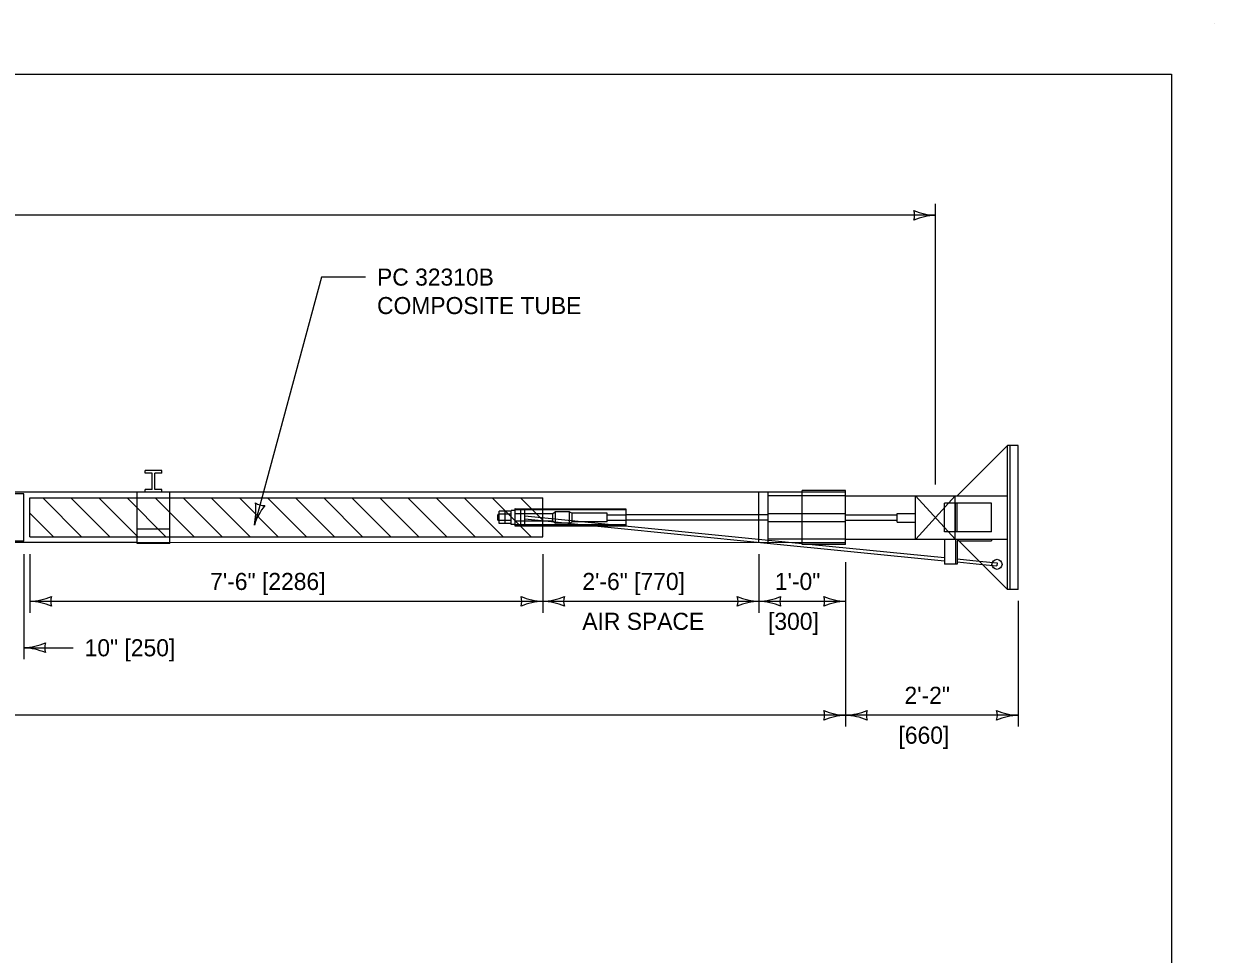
# Model space of a CAD drawing. Extents: x 49991.4 to 50021, y 49987.6 to 50011.4.
# Drawn here: x 50012.718 to 50016.9, y 49995.907 to 49999.176 of the extents above; entities that cross this region are included whole.
import ezdxf

# ---------------------------------------------------------------- set-up
doc = ezdxf.new("R2010")
doc.units = 0
for name, color, linetype in [('Level 1', 7, 'Continuous'), ('Level 2', 7, 'Continuous'), ('Level 3', 7, 'Continuous'), ('Level 4', 7, 'Continuous'), ('Level 5', 7, 'Continuous')]:
    doc.layers.add(name, color=color, linetype=linetype)

msp = doc.modelspace()

# ---------------------------------------------------------------- linework, layer by layer
at = {"layer": 'Level 1'}
for p, q in [((50016.9001, 49999.1756), (50016.9001, 49999.1756)), ((50016.1742, 49997.6945), (50015.9971, 49997.5172)), ((50016.1742, 49997.1881), (50016.1742, 49997.6945)), ((50016.2117, 49997.6945), (50016.1742, 49997.6945)), ((50016.1838, 49997.1881), (50016.1838, 49997.6945)), ((50016.2117, 49997.1881), (50016.2117, 49997.6945)), ((50013.1443, 49997.5969), (50013.1443, 49997.606)), ((50013.2033, 49997.606), (50013.1443, 49997.606)), ((50013.1693, 49997.5969), (50013.1443, 49997.5969)), ((50013.1693, 49997.5393), (50013.1693, 49997.5969)), ((50013.1784, 49997.5393), (50013.1784, 49997.5969)), ((50013.2033, 49997.5969), (50013.1784, 49997.5969)), ((50013.2033, 49997.5969), (50013.2033, 49997.606)), ((50015.4527, 49997.53), (50008.363, 49997.5304)), ((50013.1693, 49997.5393), (50013.1443, 49997.5393)), ((50013.1443, 49997.5301), (50013.1443, 49997.5393)), ((50013.2033, 49997.5393), (50013.1784, 49997.5393)), ((50013.2033, 49997.5301), (50013.2033, 49997.5393)), ((50015.4527, 49997.3467), (50015.4527, 49997.5361)), ((50015.6047, 49997.536), (50015.4527, 49997.5361)), ((50015.6047, 49997.3467), (50015.6047, 49997.536)), ((50015.6047, 49997.5173), (50016.1742, 49997.5171)), ((50015.8513, 49997.3655), (50015.8513, 49997.5172)), ((50015.8513, 49997.5172), (50015.9907, 49997.3655)), ((50015.9907, 49997.5172), (50015.8514, 49997.3655)), ((50016.1174, 49997.4921), (50015.9528, 49997.4921)), ((50015.9528, 49997.3905), (50015.9528, 49997.4921)), ((50015.9528, 49997.3932), (50015.9528, 49997.4908)), ((50015.9907, 49997.3655), (50015.9907, 49997.5172)), ((50015.9908, 49997.3905), (50015.9908, 49997.4921)), ((50015.9972, 49997.3905), (50015.9972, 49997.4921)), ((50016.1174, 49997.3905), (50016.1174, 49997.4921)), ((50015.7618, 49997.4494), (50015.6047, 49997.4494)), ((50015.7868, 49997.4494), (50015.7618, 49997.4494)), ((50015.7868, 49997.4249), (50015.7868, 49997.4557)), ((50015.7868, 49997.4557), (50015.8513, 49997.4557)), ((50015.7618, 49997.4311), (50015.6047, 49997.4311)), ((50015.7868, 49997.4311), (50015.7618, 49997.4311)), ((50015.7868, 49997.4249), (50015.8513, 49997.4249)), ((50013.2308, 49997.4004), (50013.1168, 49997.4004)), ((50013.1168, 49997.3497), (50013.1168, 49997.4003)), ((50013.2308, 49997.3498), (50013.2308, 49997.4004)), ((50015.6047, 49997.3655), (50016.1742, 49997.3653)), ((50016.1174, 49997.3905), (50015.9528, 49997.3905)), ((50015.9528, 49997.3654), (50015.9528, 49997.2768)), ((50015.9908, 49997.3654), (50015.9908, 49997.2768)), ((50016.1742, 49997.1881), (50015.9972, 49997.3654)), ((50013.1168, 49997.3529), (50011.4076, 49997.3531)), ((50013.2308, 49997.3498), (50013.1168, 49997.3498)), ((50015.4527, 49997.3527), (50013.2308, 49997.353)), ((50015.3177, 49997.3527), (50015.9528, 49997.2895)), ((50015.4275, 49997.3527), (50015.4527, 49997.3502)), ((50015.6047, 49997.3467), (50015.4527, 49997.3467)), ((50015.4878, 49997.3467), (50015.9528, 49997.3004)), ((50015.9972, 49997.359), (50015.9972, 49997.2768)), ((50016.0036, 49997.359), (50015.9972, 49997.359)), ((50015.9972, 49997.296), (50016.0741, 49997.2884)), ((50015.9972, 49997.2851), (50016.0862, 49997.2763)), ((50015.9972, 49997.2768), (50015.9528, 49997.2768)), ((50016.2117, 49997.1881), (50016.1742, 49997.1881))]:
    msp.add_line(p, q, dxfattribs=at)
msp.add_lwpolyline([(49999.3835, 49998.9992), (50016.7501, 49998.9992), (50016.7501, 49987.7988), (49999.3835, 49987.7988)], close=True, dxfattribs=at)
at = {"layer": 'Level 3'}
for p, q in [((50015.9211, 49997.5572), (50015.9211, 49998.5428)), ((50015.9211, 49998.5028), (50001.3238, 49998.5028)), ((50013.764, 49998.2858), (50013.5284, 49997.4145)), ((50013.9192, 49998.2858), (50013.764, 49998.2858)), ((50012.7185, 49997.313), (50012.7185, 49996.9436)), ((50012.7397, 49997.313), (50012.7397, 49997.1066)), ((50014.5412, 49997.3128), (50014.5412, 49997.1066)), ((50015.3009, 49997.3127), (50015.3009, 49997.1066)), ((50015.6047, 49997.2841), (50015.6047, 49996.7066)), ((50014.5412, 49997.1466), (50012.7397, 49997.1466)), ((50015.3009, 49997.1466), (50014.5412, 49997.1466)), ((50015.6047, 49997.1466), (50015.3009, 49997.1466)), ((50016.2117, 49997.1481), (50016.2117, 49996.7066)), ((50012.7185, 49996.9836), (50012.8919, 49996.9836)), ((50015.6047, 49996.7466), (50008.3123, 49996.7466)), ((50016.2117, 49996.7466), (50015.6047, 49996.7466))]:
    msp.add_line(p, q, dxfattribs=at)
for centre, radius, start, end in [((50015.9303, 49998.7249), 0.2223, 247.456, 267.6395), ((50015.7929, 49998.5028), 0.0548, 342.1388, 17.8612), ((50015.9326, 49998.2701), 0.233, 92.8273, 112.0772), ((50013.3007, 49997.4653), 0.233, 347.4771, 6.7269), ((50013.5621, 49997.5384), 0.0548, 236.7886, 272.511), ((50013.74, 49997.3471), 0.2223, 142.1058, 162.2893), ((50012.7282, 49997.3793), 0.233, 272.8273, 292.0772), ((50012.8679, 49997.1466), 0.0548, 162.1388, 197.8612), ((50014.5504, 49997.3687), 0.2223, 247.456, 267.6395), ((50014.413, 49997.1466), 0.0548, 342.1388, 17.8612), ((50014.5297, 49997.3793), 0.233, 272.8273, 292.0772), ((50014.6694, 49997.1466), 0.0548, 162.1388, 197.8612), ((50015.3101, 49997.3687), 0.2223, 247.456, 267.6395), ((50015.1727, 49997.1466), 0.0548, 342.1388, 17.8612), ((50015.2894, 49997.3793), 0.233, 272.8273, 292.0772), ((50015.4291, 49997.1466), 0.0548, 162.1388, 197.8612), ((50015.6139, 49997.3687), 0.2223, 247.456, 267.6395), ((50015.4765, 49997.1466), 0.0548, 342.1388, 17.8612), ((50012.7305, 49996.9245), 0.2223, 67.456, 87.6395), ((50014.5527, 49996.9139), 0.233, 92.8273, 112.0772), ((50014.532, 49996.9245), 0.2223, 67.456, 87.6395), ((50015.3124, 49996.9139), 0.233, 92.8273, 112.0772), ((50015.2917, 49996.9245), 0.2223, 67.456, 87.6395), ((50015.6162, 49996.9139), 0.233, 92.8273, 112.0772), ((50012.707, 49997.2163), 0.233, 272.8273, 292.0772), ((50012.8467, 49996.9836), 0.0548, 162.1388, 197.8612), ((50012.7093, 49996.7614), 0.2223, 67.456, 87.6395), ((50015.6139, 49996.9687), 0.2223, 247.456, 267.6395), ((50015.4765, 49996.7466), 0.0548, 342.1388, 17.8612), ((50015.6162, 49996.5139), 0.233, 92.8273, 112.0772), ((50015.5932, 49996.9793), 0.233, 272.8273, 292.0772), ((50015.5955, 49996.5245), 0.2223, 67.456, 87.6395), ((50015.7329, 49996.7466), 0.0548, 162.1388, 197.8612), ((50016.2209, 49996.9687), 0.2223, 247.456, 267.6395), ((50016.0835, 49996.7466), 0.0548, 342.1388, 17.8612), ((50016.2232, 49996.5139), 0.233, 92.8273, 112.0772)]:
    msp.add_arc(centre, radius, start, end, dxfattribs=at)
at = {"layer": 'Level 4'}
for p, q in [((50013.1168, 49997.4004), (50013.1168, 49997.5301)), ((50013.2308, 49997.4004), (50013.2308, 49997.5301)), ((50015.3009, 49997.3528), (50015.3009, 49997.53)), ((50015.3329, 49997.3528), (50015.333, 49997.53)), ((50015.6047, 49997.5299), (50015.4527, 49997.53)), ((50012.7185, 49997.5245), (50012.6847, 49997.5245)), ((50012.7185, 49997.3586), (50012.7185, 49997.5245)), ((50012.7397, 49997.3734), (50012.7397, 49997.51)), ((50014.5412, 49997.3731), (50014.5413, 49997.5099)), ((50015.6047, 49997.5173), (50015.3329, 49997.5174)), ((50014.3837, 49997.4323), (50014.3838, 49997.4509)), ((50014.3884, 49997.454), (50014.3838, 49997.4509)), ((50014.3884, 49997.4197), (50014.3884, 49997.4636)), ((50014.4305, 49997.4636), (50014.3884, 49997.4636)), ((50014.3884, 49997.4294), (50014.3884, 49997.454)), ((50014.4305, 49997.4527), (50014.3884, 49997.4528)), ((50014.4095, 49997.4197), (50014.4095, 49997.4636)), ((50014.4305, 49997.4171), (50014.4305, 49997.4662)), ((50014.4449, 49997.4109), (50014.4449, 49997.4723)), ((50014.8335, 49997.4676), (50014.4449, 49997.4677)), ((50014.5769, 49997.4538), (50014.4449, 49997.4539)), ((50014.4644, 49997.4155), (50014.4644, 49997.4677)), ((50014.4787, 49997.4155), (50014.4787, 49997.4677)), ((50014.4787, 49997.4471), (50015.4275, 49997.3527)), ((50014.5861, 49997.4615), (50014.5769, 49997.4538)), ((50014.5769, 49997.4293), (50014.5769, 49997.4538)), ((50014.586, 49997.4215), (50014.5861, 49997.4615)), ((50014.6352, 49997.4615), (50014.5861, 49997.4615)), ((50014.6351, 49997.4215), (50014.6352, 49997.4615)), ((50014.6352, 49997.4615), (50014.6445, 49997.4567)), ((50014.6444, 49997.4259), (50014.6445, 49997.4567)), ((50014.7674, 49997.4567), (50014.6445, 49997.4567)), ((50014.7674, 49997.4259), (50014.7674, 49997.4567)), ((50014.7674, 49997.4505), (50014.8336, 49997.4505)), ((50014.8335, 49997.4722), (50014.8336, 49997.4108)), ((50015.333, 49997.4502), (50014.8336, 49997.4505)), ((50015.6047, 49997.4546), (50015.3329, 49997.4546)), ((50014.3884, 49997.4294), (50014.3837, 49997.4323)), ((50014.4305, 49997.4306), (50014.3884, 49997.4306)), ((50014.4306, 49997.4197), (50014.3884, 49997.4197)), ((50014.4449, 49997.4294), (50014.5769, 49997.4293)), ((50014.8336, 49997.4154), (50014.4449, 49997.4155)), ((50014.8336, 49997.4108), (50014.4449, 49997.4109)), ((50014.4787, 49997.4362), (50015.3177, 49997.3527)), ((50014.5769, 49997.4293), (50014.586, 49997.4215)), ((50014.6351, 49997.4215), (50014.586, 49997.4215)), ((50014.6351, 49997.4215), (50014.6444, 49997.4259)), ((50014.7674, 49997.4259), (50014.6444, 49997.4259)), ((50014.7679, 49997.4322), (50014.8335, 49997.4322)), ((50015.3329, 49997.4319), (50014.8335, 49997.4322)), ((50015.6047, 49997.4263), (50015.3329, 49997.4263)), ((50015.6047, 49997.3655), (50015.3329, 49997.3654)), ((50016.1174, 49997.3653), (50016.1174, 49997.359)), ((50012.7185, 49997.3586), (50012.6847, 49997.3586)), ((50015.6047, 49997.3528), (50015.4527, 49997.3528)), ((50016.0036, 49997.359), (50016.1174, 49997.359)), ((50016.0741, 49997.2884), (50016.1377, 49997.2821)), ((50016.1377, 49997.2821), (50016.1366, 49997.2713)), ((50016.0862, 49997.2763), (50016.1366, 49997.2713))]:
    msp.add_line(p, q, dxfattribs=at)
for points in [[(50012.7397, 49997.5101), (50014.5413, 49997.5101)], [(50014.4449, 49997.4662), (50014.4305, 49997.4662)], [(50014.4449, 49997.4723), (50014.8335, 49997.4722)], [(50014.4448, 49997.4171), (50014.4305, 49997.4171)], [(50012.7397, 49997.3732), (50014.5412, 49997.3732)], [(50013.1168, 49997.353), (50013.2308, 49997.353)]]:
    msp.add_lwpolyline(points, dxfattribs=at)
msp.add_circle((50016.1371, 49997.2767), 0.0177, dxfattribs=at)
at = {"layer": 'Level 5'}
for p, q in [((50012.9215, 49997.3732), (50012.7848, 49997.5101)), ((50013.0202, 49997.3732), (50012.8835, 49997.5101)), ((50013.1189, 49997.3732), (50012.9822, 49997.5101)), ((50013.2176, 49997.3732), (50013.0809, 49997.5101)), ((50013.3163, 49997.3732), (50013.1796, 49997.5101)), ((50013.415, 49997.3732), (50013.2783, 49997.5101)), ((50013.5137, 49997.3732), (50013.377, 49997.5101)), ((50013.6124, 49997.3732), (50013.4757, 49997.5101)), ((50013.7111, 49997.3732), (50013.5744, 49997.5101)), ((50013.8098, 49997.3732), (50013.6731, 49997.5101)), ((50013.9085, 49997.3732), (50013.7718, 49997.5101)), ((50014.0072, 49997.3732), (50013.8705, 49997.5101)), ((50014.1059, 49997.3732), (50013.9692, 49997.5101)), ((50014.2046, 49997.3732), (50014.0679, 49997.5101)), ((50014.3033, 49997.3732), (50014.1666, 49997.5101)), ((50014.402, 49997.3732), (50014.2653, 49997.5101)), ((50014.5007, 49997.3732), (50014.364, 49997.5101)), ((50014.5412, 49997.4314), (50014.4627, 49997.5101)), ((50012.8228, 49997.3732), (50012.7397, 49997.4564))]:
    msp.add_line(p, q, dxfattribs=at)

# ---------------------------------------------------------------- texts
at = {"layer": 'Level 2'}
for s, p in [('PC 32310B', (50013.9592, 49998.2558)), ('COMPOSITE TUBE', (50013.9592, 49998.1558)), ('7\'-6" [2286]', (50013.3729, 49997.1866)), ('2\'-6" [770]', (50014.6804, 49997.1866)), ('1\'-0"', (50015.3567, 49997.1866)), ('AIR SPACE', (50014.6803, 49997.0466)), ('[300]', (50015.3327, 49997.0466)), ('10" [250]', (50012.9319, 49996.9536)), ('2\'-2"', (50015.8121, 49996.7866)), ('[660]', (50015.7911, 49996.6466))]:
    msp.add_text(s, height=0.06, dxfattribs=at).set_placement(p)

doc.saveas('drawing.dxf')
